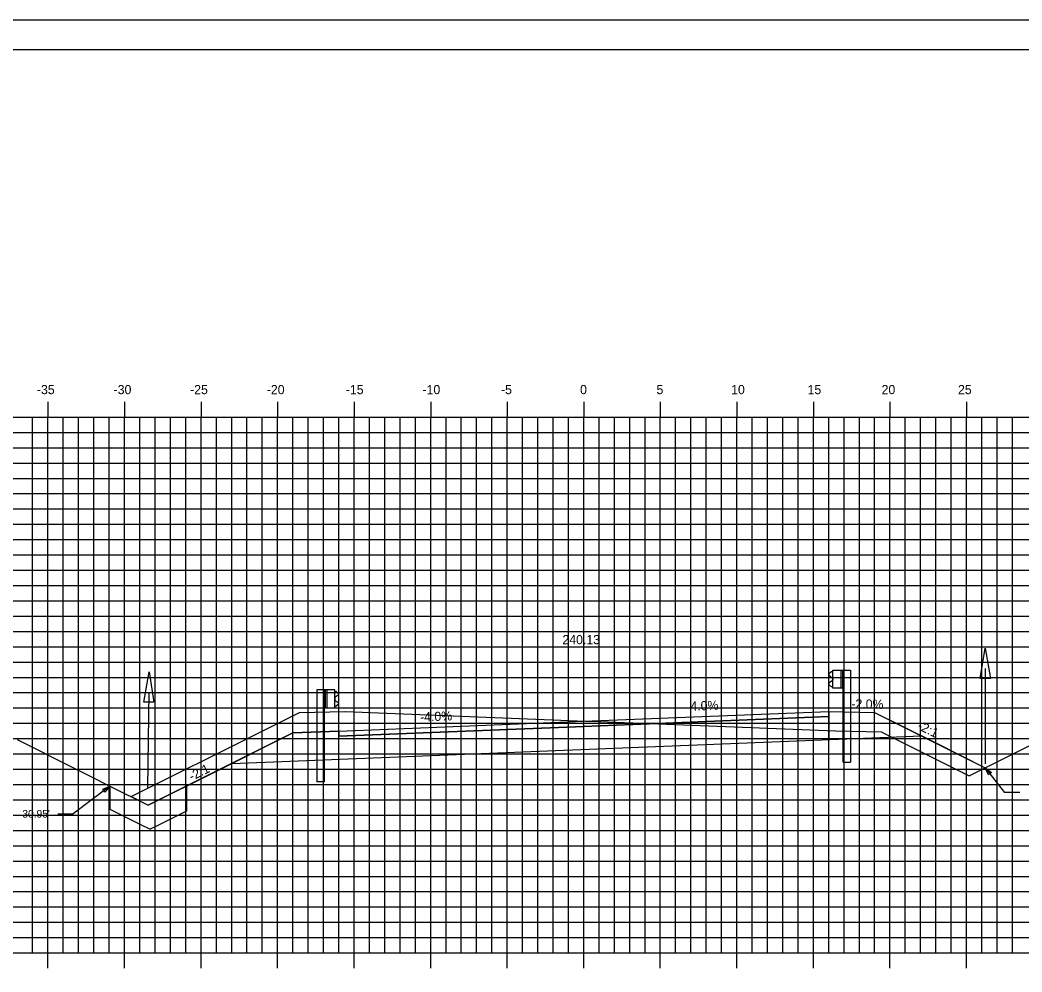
# Model space of a CAD drawing. Extents: x 1170543 to 1177585, y 609599 to 610623.
# Drawn here: x 1173546.2 to 1173611.6, y 609646.6 to 609708.8 of the extents above; entities that cross this region are included whole.
import ezdxf

# ---------------------------------------------------------------- set-up
doc = ezdxf.new("R2010")
doc.units = 0
for name, color, linetype in [('ANNOTATION', 7, 'Continuous'), ('BORDER', 7, 'Continuous'), ('D_Drainage_Ditch_Line', 7, 'Continuous'), ('D_Guardrail_Beam_Lt', 7, 'Continuous'), ('D_Guardrail_Beam_Rt', 7, 'Continuous'), ('D_Roadway_Centerline', 7, 'Continuous'), ('D_Roadway_Centerline_Text', 7, 'Continuous'), ('D_Roadway_Edge_Shoulder', 7, 'Continuous'), ('D_Roadway_Edge_TW', 7, 'Continuous'), ('D_Roadway_Pavement', 7, 'Continuous'), ('D_Roadway_SlopeLines', 7, 'Continuous'), ('D_Roadway_SubGrade', 7, 'Continuous'), ('H_V ANNOTATION', 7, 'Continuous'), ('MAJOR', 7, 'Continuous'), ('MINOR', 7, 'Continuous'), ('PATTERNING', 7, 'Continuous'), ('PLOT BOUNDARY', 7, 'Continuous'), ('S_Roadway_Centerline', 7, 'Continuous'), ('SHADING', 7, 'Continuous')]:
    doc.layers.add(name, color=color, linetype=linetype)

msp = doc.modelspace()

# ---------------------------------------------------------------- linework, layer by layer
at = {"layer": 'ANNOTATION'}
for p, q in [((1173609.246, 609659.971), (1173610.498, 609658.34)), ((1173552.066, 609658.77), (1173549.659, 609656.958)), ((1173552.066, 609658.77), (1173554.566, 609657.52)), ((1173557.066, 609658.77), (1173557.066, 609657.139)), ((1173611.498, 609658.34), (1173610.498, 609658.34)), ((1173548.659, 609656.958), (1173549.659, 609656.958)), ((1173557.066, 609657.139), (1173555.066, 609656.139)), ((1173555.066, 609656.139), (1173554.697, 609655.954))]:
    msp.add_line(p, q, dxfattribs=at)
for points in [[(1173609.451, 609659.498), (1173609.246, 609659.971), (1173609.65, 609659.651)], [(1173551.591, 609658.569), (1173552.066, 609658.77), (1173551.741, 609658.369)]]:
    msp.add_lwpolyline(points, close=True, dxfattribs=at)
msp.add_lwpolyline([(1173552.066, 609658.77), (1173552.066, 609657.27), (1173554.066, 609656.27), (1173554.697, 609655.954)], dxfattribs=at)
at = {"layer": 'BORDER'}
msp.add_line((1173668.017, 609706.872), (1173508.017, 609706.872), dxfattribs=at)
at = {"layer": 'D_Drainage_Ditch_Line'}
for p, q in [((1173609.246, 609666.461), (1173609.246, 609660.218)), ((1173554.611, 609664.912), (1173554.519, 609658.67))]:
    msp.add_line(p, q, dxfattribs=at)
for points in [[(1173609.574, 609665.805), (1173608.918, 609665.805), (1173609.246, 609667.774)], [(1173554.929, 609664.252), (1173554.273, 609664.261), (1173554.63, 609666.225)]]:
    msp.add_lwpolyline(points, close=True, dxfattribs=at)
at = {"layer": 'D_Guardrail_Beam_Lt'}
for p, q in [((1173565.588, 609665.051), (1173565.588, 609659.051)), ((1173566.059, 609665.051), (1173565.588, 609665.051)), ((1173566.746, 609665.051), (1173566.059, 609665.051)), ((1173566.059, 609665.051), (1173566.059, 609663.884)), ((1173566.121, 609665.051), (1173566.121, 609663.884)), ((1173566.226, 609665.051), (1173566.226, 609663.884)), ((1173566.746, 609663.884), (1173566.746, 609665.051)), ((1173566.746, 609664.968), (1173566.821, 609664.953)), ((1173566.98, 609664.703), (1173566.784, 609664.567)), ((1173566.836, 609664.946), (1173566.98, 609664.846)), ((1173566.751, 609664.503), (1173566.751, 609664.433)), ((1173566.784, 609664.368), (1173566.98, 609664.232)), ((1173566.98, 609664.089), (1173566.836, 609663.989)), ((1173566.059, 609663.884), (1173566.746, 609663.884)), ((1173566.08, 609659.051), (1173566.08, 609663.884)), ((1173566.821, 609663.982), (1173566.746, 609663.968)), ((1173566.08, 609659.051), (1173565.588, 609659.051))]:
    msp.add_line(p, q, dxfattribs=at)
for centre, major_axis, start_param, end_param in [((1173566.812, 609664.912), (0.0417, 0), 0.959931, 1.376053), ((1173566.93, 609664.775), (0.0877, 0), 5.323254, 7.243116), ((1173566.83, 609664.503), (-0.0789, 0), 5.323254, 6.283185), ((1173566.83, 609664.433), (-0.0789, 0), 6.283185, 7.243116), ((1173566.93, 609664.161), (0.0877, 0), 5.323254, 7.243116), ((1173566.812, 609664.023), (0.0417, 0), 4.907132, 5.323254)]:
    msp.add_ellipse(centre, major_axis=major_axis, ratio=0.995501, start_param=start_param, end_param=end_param, dxfattribs=at)
at = {"layer": 'D_Guardrail_Beam_Rt'}
for p, q in [((1173599.198, 609666.226), (1173599.055, 609666.126)), ((1173599.288, 609666.248), (1173599.214, 609666.233)), ((1173599.288, 609666.331), (1173599.976, 609666.331)), ((1173599.288, 609665.164), (1173599.288, 609666.331)), ((1173599.809, 609666.331), (1173599.809, 609665.164)), ((1173599.913, 609666.331), (1173599.913, 609665.164)), ((1173599.976, 609666.331), (1173600.446, 609666.331)), ((1173599.976, 609666.331), (1173599.976, 609665.164)), ((1173600.446, 609666.331), (1173600.446, 609660.331)), ((1173599.055, 609665.983), (1173599.25, 609665.847)), ((1173599.25, 609665.648), (1173599.055, 609665.512)), ((1173599.055, 609665.369), (1173599.198, 609665.269)), ((1173599.284, 609665.783), (1173599.284, 609665.713)), ((1173599.214, 609665.262), (1173599.288, 609665.248)), ((1173599.976, 609665.164), (1173599.288, 609665.164)), ((1173599.955, 609660.331), (1173599.955, 609665.164)), ((1173599.955, 609660.331), (1173600.446, 609660.331))]:
    msp.add_line(p, q, dxfattribs=at)
for centre, major_axis, start_param, end_param in [((1173599.105, 609666.055), (-0.0877, 0), 5.323254, 7.243116), ((1173599.222, 609666.192), (-0.0417, 0), 4.907132, 5.323254), ((1173599.105, 609665.441), (-0.0877, 0), 5.323254, 7.243116), ((1173599.205, 609665.783), (0.0789, 0), 0, 0.959931), ((1173599.205, 609665.713), (0.0789, 0), 5.323254, 6.283185), ((1173599.222, 609665.303), (-0.0417, 0), 0.959931, 1.376053)]:
    msp.add_ellipse(centre, major_axis=major_axis, ratio=0.995501, start_param=start_param, end_param=end_param, dxfattribs=at)
at = {"layer": 'D_Roadway_Centerline'}
for p, q in [((1173583.017, 609663.005), (1173599.017, 609663.645)), ((1173599.017, 609663.645), (1173602.017, 609663.585)), ((1173602.017, 609663.585), (1173606.005, 609661.592)), ((1173567.017, 609662.365), (1173583.017, 609663.005)), ((1173558.945, 609659.709), (1173564.017, 609662.245)), ((1173564.017, 609662.245), (1173567.017, 609662.365)), ((1173606.005, 609661.592), (1173609.246, 609659.971)), ((1173554.566, 609657.52), (1173558.945, 609659.709))]:
    msp.add_line(p, q, dxfattribs=at)
at = {"layer": 'D_Roadway_Edge_Shoulder'}
for points in [[(1173599.017, 609663.645), (1173599.017, 609663.312)], [(1173567.017, 609662.365), (1173567.017, 609662.032)]]:
    msp.add_lwpolyline(points, dxfattribs=at)
at = {"layer": 'D_Roadway_Edge_TW'}
msp.add_lwpolyline([(1173567.017, 609662.032), (1173567.017, 609662.365), (1173583.017, 609663.005), (1173599.017, 609663.645), (1173599.017, 609663.312), (1173583.017, 609662.672)], close=True, dxfattribs=at)
at = {"layer": 'D_Roadway_Pavement'}
msp.add_lwpolyline([(1173567.017, 609662.032), (1173567.017, 609662.032), (1173583.017, 609662.672), (1173599.017, 609663.312), (1173599.017, 609663.312), (1173583.017, 609662.672)], close=True, dxfattribs=at)
for points in [[(1173599.017, 609663.312), (1173599.017, 609663.312)], [(1173599.017, 609663.312), (1173599.017, 609663.312)], [(1173567.017, 609662.032), (1173567.017, 609662.032)], [(1173567.017, 609662.032), (1173567.017, 609662.032)]]:
    msp.add_lwpolyline(points, dxfattribs=at)
at = {"layer": 'D_Roadway_SlopeLines'}
msp.add_line((1173553.453, 609658.078), (1173554.566, 609657.52), dxfattribs=at)
for points in [[(1173602.017, 609663.585), (1173609.246, 609659.971)], [(1173564.017, 609662.245), (1173554.566, 609657.52)]]:
    msp.add_lwpolyline(points, dxfattribs=at)
at = {"layer": 'D_Roadway_SubGrade'}
for p, q in [((1173583.017, 609662.672), (1173599.017, 609663.312)), ((1173599.017, 609663.312), (1173599.017, 609661.812)), ((1173564.017, 609662.245), (1173558.945, 609659.709)), ((1173567.017, 609662.365), (1173564.017, 609662.245)), ((1173567.017, 609662.032), (1173583.017, 609662.672)), ((1173567.017, 609660.532), (1173567.017, 609662.365)), ((1173567.017, 609660.532), (1173567.017, 609662.032))]:
    msp.add_line(p, q, dxfattribs=at)
at = {"layer": 'MAJOR'}
for p, q in [((1173548.017, 609683.874), (1173548.017, 609682.872)), ((1173553.017, 609683.874), (1173553.017, 609682.872)), ((1173558.017, 609683.874), (1173558.017, 609682.872)), ((1173563.017, 609683.874), (1173563.017, 609682.872)), ((1173568.017, 609683.874), (1173568.017, 609682.872)), ((1173573.017, 609683.874), (1173573.017, 609682.872)), ((1173578.017, 609683.874), (1173578.017, 609682.872)), ((1173583.017, 609683.874), (1173583.017, 609682.872)), ((1173588.017, 609683.874), (1173588.017, 609682.872)), ((1173593.017, 609683.874), (1173593.017, 609682.872)), ((1173598.017, 609683.874), (1173598.017, 609682.872)), ((1173603.017, 609683.874), (1173603.017, 609682.872)), ((1173608.017, 609683.874), (1173608.017, 609682.872)), ((1173513.017, 609682.872), (1173653.017, 609682.872)), ((1173513.017, 609682.872), (1173653.017, 609682.872)), ((1173548.017, 609647.872), (1173548.017, 609682.872)), ((1173553.017, 609647.872), (1173553.017, 609682.872)), ((1173558.017, 609647.872), (1173558.017, 609682.872)), ((1173563.017, 609647.872), (1173563.017, 609682.872)), ((1173568.017, 609647.872), (1173568.017, 609682.872)), ((1173573.017, 609647.872), (1173573.017, 609682.872)), ((1173578.017, 609647.872), (1173578.017, 609682.872)), ((1173583.017, 609647.872), (1173583.017, 609682.872)), ((1173588.017, 609647.872), (1173588.017, 609682.872)), ((1173593.017, 609647.872), (1173593.017, 609682.872)), ((1173598.017, 609647.872), (1173598.017, 609682.872)), ((1173603.017, 609647.872), (1173603.017, 609682.872)), ((1173608.017, 609647.872), (1173608.017, 609682.872)), ((1173513.017, 609677.872), (1173653.017, 609677.872)), ((1173513.017, 609672.872), (1173653.017, 609672.872)), ((1173513.017, 609667.872), (1173653.017, 609667.872)), ((1173513.017, 609662.872), (1173653.017, 609662.872)), ((1173513.017, 609657.872), (1173653.017, 609657.872)), ((1173513.017, 609652.872), (1173653.017, 609652.872)), ((1173513.017, 609647.872), (1173653.017, 609647.872)), ((1173513.017, 609647.872), (1173653.017, 609647.872)), ((1173548.017, 609646.87), (1173548.017, 609647.872)), ((1173553.017, 609646.87), (1173553.017, 609647.872)), ((1173558.017, 609646.87), (1173558.017, 609647.872)), ((1173563.017, 609646.87), (1173563.017, 609647.872)), ((1173568.017, 609646.87), (1173568.017, 609647.872)), ((1173573.017, 609646.87), (1173573.017, 609647.872)), ((1173578.017, 609646.87), (1173578.017, 609647.872)), ((1173583.017, 609646.87), (1173583.017, 609647.872)), ((1173588.017, 609646.87), (1173588.017, 609647.872)), ((1173593.017, 609646.87), (1173593.017, 609647.872)), ((1173598.017, 609646.87), (1173598.017, 609647.872)), ((1173603.017, 609646.87), (1173603.017, 609647.872)), ((1173608.017, 609646.87), (1173608.017, 609647.872))]:
    msp.add_line(p, q, dxfattribs=at)
at = {"layer": 'MINOR'}
for p, q in [((1173547.017, 609647.872), (1173547.017, 609682.872)), ((1173549.017, 609647.872), (1173549.017, 609682.872)), ((1173550.017, 609647.872), (1173550.017, 609682.872)), ((1173551.017, 609647.872), (1173551.017, 609682.872)), ((1173552.017, 609647.872), (1173552.017, 609682.872)), ((1173554.017, 609647.872), (1173554.017, 609682.872)), ((1173555.017, 609647.872), (1173555.017, 609682.872)), ((1173556.017, 609647.872), (1173556.017, 609682.872)), ((1173557.017, 609647.872), (1173557.017, 609682.872)), ((1173559.017, 609647.872), (1173559.017, 609682.872)), ((1173560.017, 609647.872), (1173560.017, 609682.872)), ((1173561.017, 609647.872), (1173561.017, 609682.872)), ((1173562.017, 609647.872), (1173562.017, 609682.872)), ((1173564.017, 609647.872), (1173564.017, 609682.872)), ((1173565.017, 609647.872), (1173565.017, 609682.872)), ((1173566.017, 609647.872), (1173566.017, 609682.872)), ((1173567.017, 609647.872), (1173567.017, 609682.872)), ((1173569.017, 609647.872), (1173569.017, 609682.872)), ((1173570.017, 609647.872), (1173570.017, 609682.872)), ((1173571.017, 609647.872), (1173571.017, 609682.872)), ((1173572.017, 609647.872), (1173572.017, 609682.872)), ((1173574.017, 609647.872), (1173574.017, 609682.872)), ((1173575.017, 609647.872), (1173575.017, 609682.872)), ((1173576.017, 609647.872), (1173576.017, 609682.872)), ((1173577.017, 609647.872), (1173577.017, 609682.872)), ((1173579.017, 609647.872), (1173579.017, 609682.872)), ((1173580.017, 609647.872), (1173580.017, 609682.872)), ((1173581.017, 609647.872), (1173581.017, 609682.872)), ((1173582.017, 609647.872), (1173582.017, 609682.872)), ((1173584.017, 609647.872), (1173584.017, 609682.872)), ((1173585.017, 609647.872), (1173585.017, 609682.872)), ((1173586.017, 609647.872), (1173586.017, 609682.872)), ((1173587.017, 609647.872), (1173587.017, 609682.872)), ((1173589.017, 609647.872), (1173589.017, 609682.872)), ((1173590.017, 609647.872), (1173590.017, 609682.872)), ((1173591.017, 609647.872), (1173591.017, 609682.872)), ((1173592.017, 609647.872), (1173592.017, 609682.872)), ((1173594.017, 609647.872), (1173594.017, 609682.872)), ((1173595.017, 609647.872), (1173595.017, 609682.872)), ((1173596.017, 609647.872), (1173596.017, 609682.872)), ((1173597.017, 609647.872), (1173597.017, 609682.872)), ((1173599.017, 609647.872), (1173599.017, 609682.872)), ((1173600.017, 609647.872), (1173600.017, 609682.872)), ((1173601.017, 609647.872), (1173601.017, 609682.872)), ((1173602.017, 609647.872), (1173602.017, 609682.872)), ((1173604.017, 609647.872), (1173604.017, 609682.872)), ((1173605.017, 609647.872), (1173605.017, 609682.872)), ((1173606.017, 609647.872), (1173606.017, 609682.872)), ((1173607.017, 609647.872), (1173607.017, 609682.872)), ((1173609.017, 609647.872), (1173609.017, 609682.872)), ((1173610.017, 609647.872), (1173610.017, 609682.872)), ((1173611.017, 609647.872), (1173611.017, 609682.872)), ((1173513.017, 609681.872), (1173653.017, 609681.872)), ((1173513.017, 609680.872), (1173653.017, 609680.872)), ((1173513.017, 609679.872), (1173653.017, 609679.872)), ((1173513.017, 609678.872), (1173653.017, 609678.872)), ((1173513.017, 609676.872), (1173653.017, 609676.872)), ((1173513.017, 609675.872), (1173653.017, 609675.872)), ((1173513.017, 609674.872), (1173653.017, 609674.872)), ((1173513.017, 609673.872), (1173653.017, 609673.872)), ((1173513.017, 609671.872), (1173653.017, 609671.872)), ((1173513.017, 609670.872), (1173653.017, 609670.872)), ((1173513.017, 609669.872), (1173653.017, 609669.872)), ((1173513.017, 609668.872), (1173653.017, 609668.872)), ((1173513.017, 609666.872), (1173653.017, 609666.872)), ((1173513.017, 609665.872), (1173653.017, 609665.872)), ((1173513.017, 609664.872), (1173653.017, 609664.872)), ((1173513.017, 609663.872), (1173653.017, 609663.872)), ((1173513.017, 609661.872), (1173653.017, 609661.872)), ((1173513.017, 609660.872), (1173653.017, 609660.872)), ((1173513.017, 609659.872), (1173653.017, 609659.872)), ((1173513.017, 609658.872), (1173653.017, 609658.872)), ((1173513.017, 609656.872), (1173653.017, 609656.872)), ((1173513.017, 609655.872), (1173653.017, 609655.872)), ((1173513.017, 609654.872), (1173653.017, 609654.872)), ((1173513.017, 609653.872), (1173653.017, 609653.872)), ((1173513.017, 609651.872), (1173653.017, 609651.872)), ((1173513.017, 609650.872), (1173653.017, 609650.872)), ((1173513.017, 609649.872), (1173653.017, 609649.872)), ((1173513.017, 609648.872), (1173653.017, 609648.872))]:
    msp.add_line(p, q, dxfattribs=at)
at = {"layer": 'PATTERNING'}
msp.add_lwpolyline([(1173554.566, 609657.52), (1173556.566, 609658.52), (1173557.066, 609658.77)], dxfattribs=at)
at = {"layer": 'PLOT BOUNDARY'}
msp.add_lwpolyline([(1173499.924, 609598.813), (1173669.924, 609598.813), (1173669.924, 609708.813), (1173499.924, 609708.813)], close=True, dxfattribs=at)
at = {"layer": 'S_Roadway_Centerline'}
msp.add_lwpolyline([(1173546.009, 609661.819), (1173553.242, 609658.183), (1173553.453, 609658.078), (1173561.746, 609662.227), (1173561.797, 609662.252), (1173564.445, 609663.577), (1173567.422, 609663.638), (1173567.446, 609663.638), (1173583.14, 609663.016), (1173583.141, 609663.016), (1173583.173, 609663.015), (1173583.448, 609663.004), (1173583.45, 609663.004), (1173599.456, 609662.369), (1173599.48, 609662.369), (1173602.458, 609662.31), (1173602.493, 609662.292), (1173608.099, 609659.493), (1173608.191, 609659.447), (1173617.969, 609664.31)], dxfattribs=at)
at = {"layer": 'SHADING'}
msp.add_line((1173560.032, 609660.253), (1173605.079, 609662.055), dxfattribs=at)

# ---------------------------------------------------------------- texts
at = {"layer": 'ANNOTATION'}
for s, rotation, p in [('4.0%', 2.29061, (1173589.994, 609663.685)), ('-2.0%', 358.85424, (1173600.492, 609663.85)), ('-4.0%', 2.29061, (1173572.333, 609662.979)), ('-2:1', 333.43495, (1173604.76, 609662.519)), ('-2:1', 26.56505, (1173557.405, 609659.094))]:
    msp.add_text(s, height=0.6, rotation=rotation, dxfattribs=at).set_placement(p)
msp.add_text("30.95'", height=0.5, dxfattribs=at).set_placement((1173546.342, 609656.708))
at = {"layer": 'D_Roadway_Centerline'}
for s, p in [('C', (1173583.012, 609663.005)), ('L', (1173583.017, 609662.998))]:
    msp.add_text(s, height=0.0146, dxfattribs=at).set_placement(p)
at = {"layer": 'D_Roadway_Centerline_Text'}
msp.add_text('240.13', height=0.6, dxfattribs=at).set_placement((1173581.623, 609668.037))
at = {"layer": 'H_V ANNOTATION'}
for s, p in [('-35', (1173547.297, 609684.372)), ('-30', (1173552.305, 609684.372)), ('-25', (1173557.303, 609684.372)), ('-20', (1173562.311, 609684.372)), ('-15', (1173567.474, 609684.372)), ('-10', (1173572.482, 609684.372)), ('-5', (1173577.608, 609684.372)), ('0', (1173582.776, 609684.372)), ('5', (1173587.768, 609684.372)), ('10', (1173592.643, 609684.372)), ('15', (1173597.635, 609684.372)), ('20', (1173602.471, 609684.372)), ('25', (1173607.463, 609684.372))]:
    msp.add_text(s, height=0.6, dxfattribs=at).set_placement(p)

doc.saveas('drawing.dxf')
